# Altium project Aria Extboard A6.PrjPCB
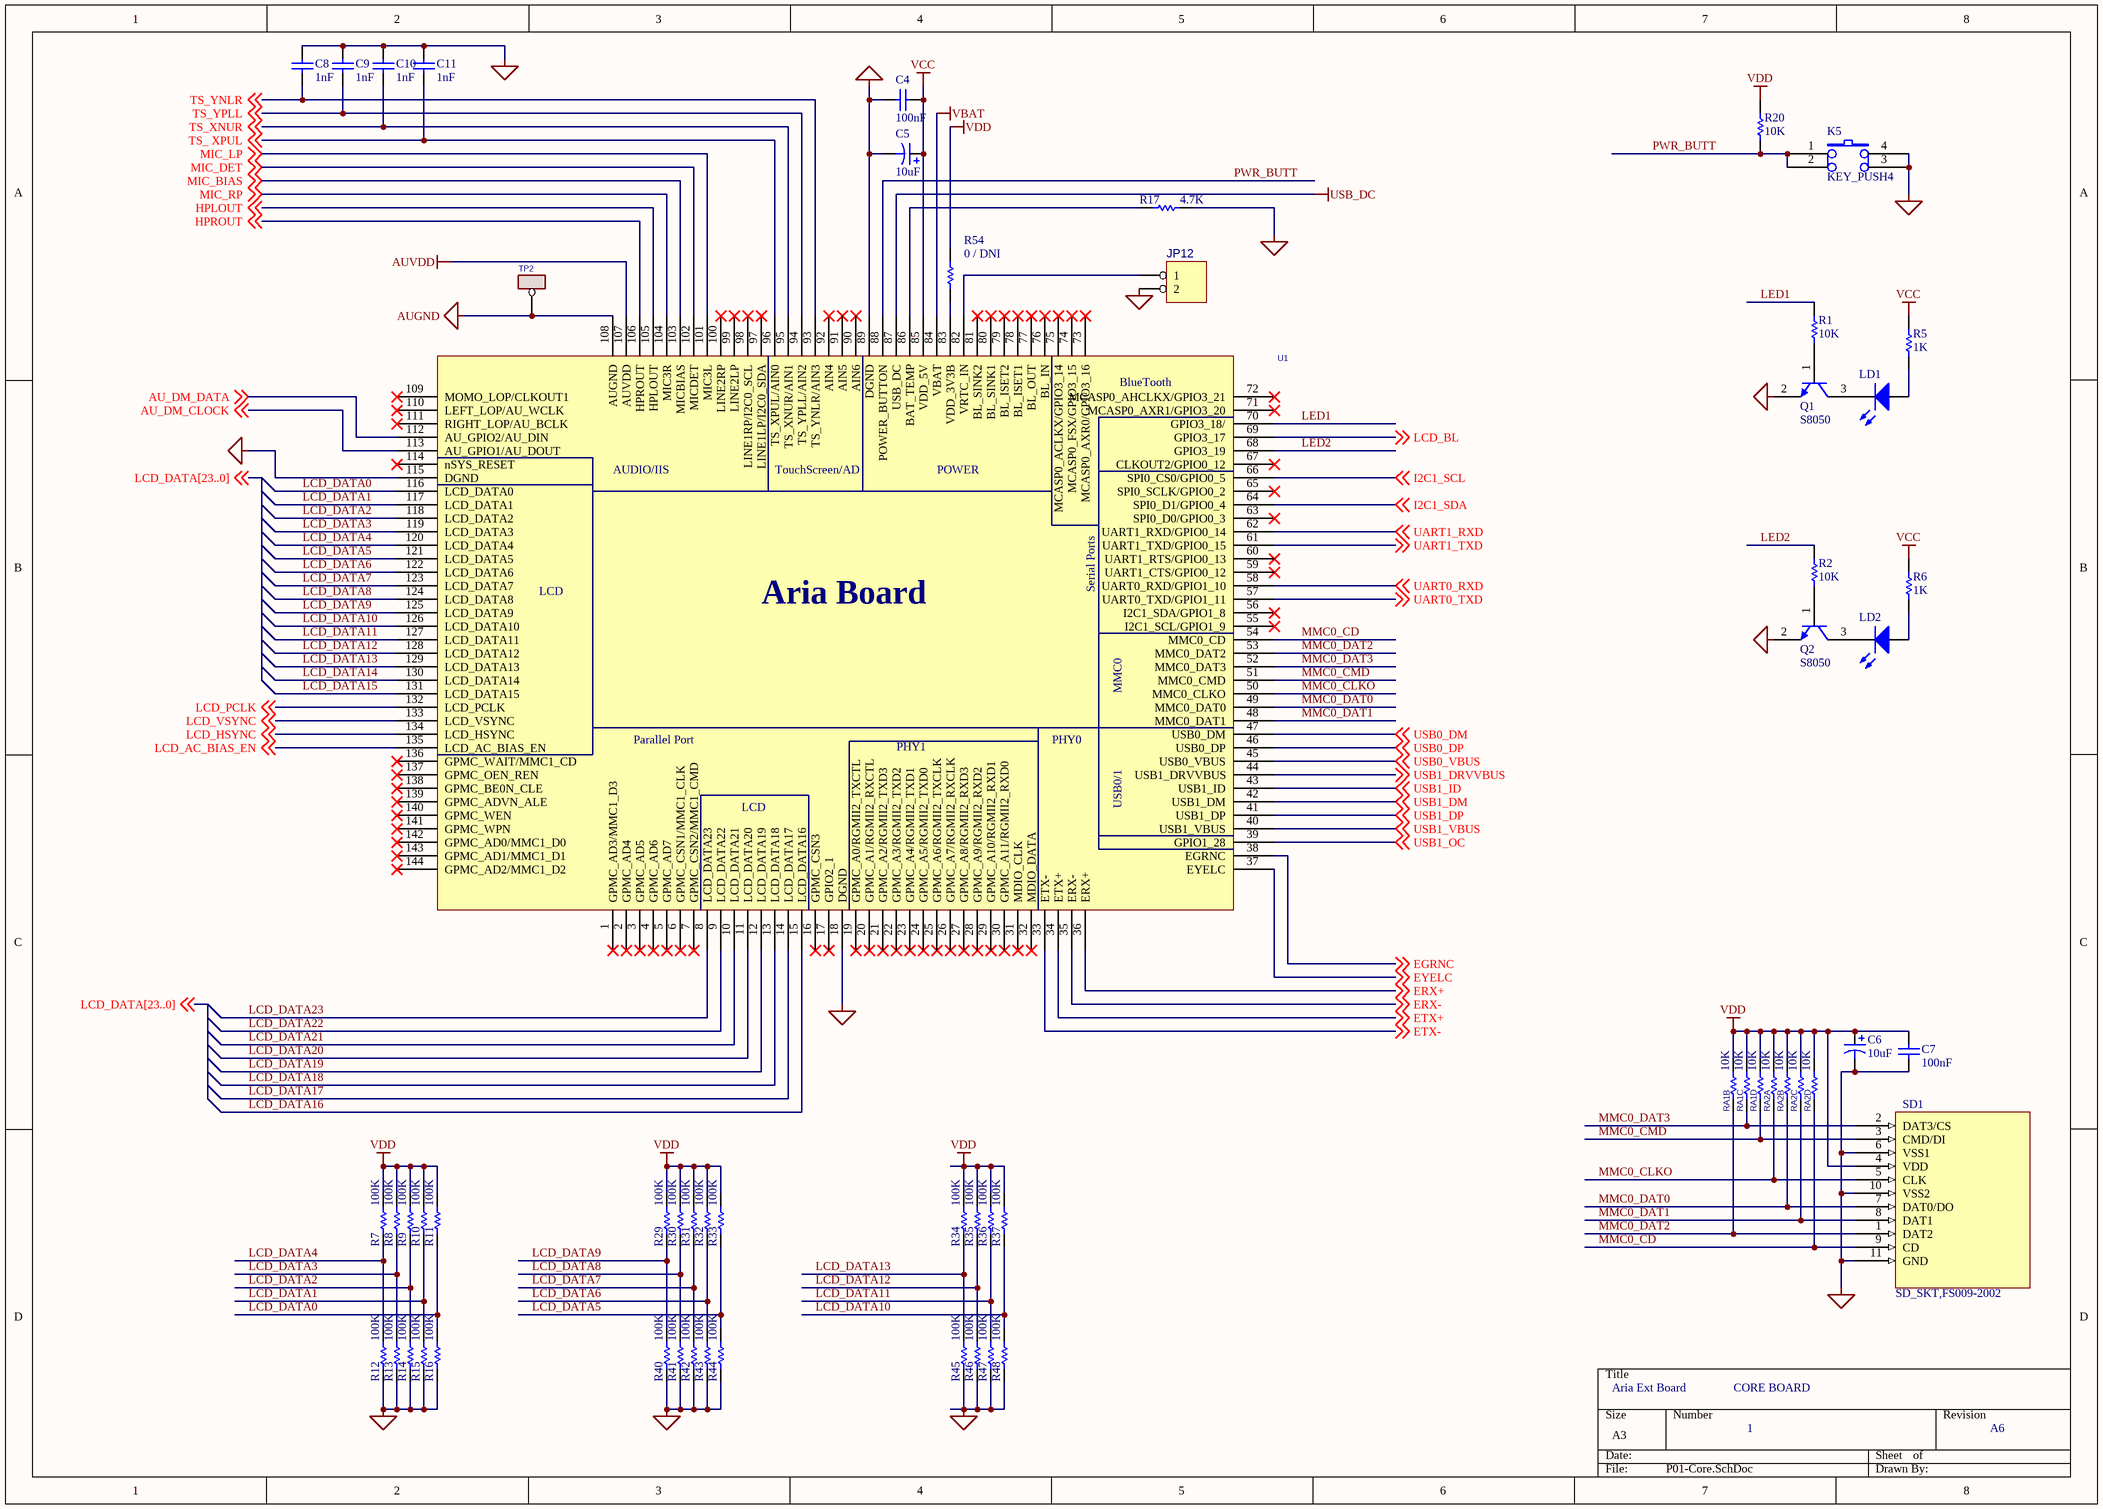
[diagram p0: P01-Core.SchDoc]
4 sheets, 128 parts. Net scope: global (net labels, ports and power ports of the same name join across sheets).
Board file: ExtBoard.PcbDoc
Sheets:
  P01-Core.SchDoc
  P02-Audio&Net.SchDoc
  P03-LCD.SchDoc
  P04-Connect.SchDoc

## Sheet P01-Core.SchDoc
size A3

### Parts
C4  100nF  [U1608-0603]
C5  10uF  [CC3216-1206]
C6  10uF  [CC3216-1206]
C7  100nF  [U1608-0603]
C8  1nF  [U1608-0603]
C9  1nF  [U1608-0603]
C10  1nF  [U1608-0603]
C11  1nF  [U1608-0603]
JP12  HEADER 2  [SIP\2P]  (value not drawn)
K5  KEY_PUSH4  [KEY6.5X6.5B]
LD1  LED  [LED1206]  (value not drawn)
LD2  LED  [LED1206]  (value not drawn)
Q1  S8050  [SOT23]
Q2  S8050  [SOT23]
R1  10K  [U1608-0603]
R2  10K  [U1608-0603]
R5  1K  [U1608-0603]
R6  1K  [U1608-0603]
R7  100K  [U1608-0603]
R8  100K  [U1608-0603]
R9  100K  [U1608-0603]
R10  100K  [U1608-0603]
R11  100K  [U1608-0603]
R12  100K  [U1608-0603]
R13  100K  [U1608-0603]
R14  100K  [U1608-0603]
R15  100K  [U1608-0603]
R16  100K  [U1608-0603]
R17  4.7K  [U1608-0603]
R20  10K  [U1608-0603]
R29  100K  [U1608-0603]
R30  100K  [U1608-0603]
R31  100K  [U1608-0603]
R32  100K  [U1608-0603]
R33  100K  [U1608-0603]
R34  100K  [U1608-0603]
R35  100K  [U1608-0603]
R36  100K  [U1608-0603]
R37  100K  [U1608-0603]
R40  100K  [U1608-0603]
R41  100K  [U1608-0603]
R42  100K  [U1608-0603]
R43  100K  [U1608-0603]
R44  100K  [U1608-0603]
R45  100K  [U1608-0603]
R46  100K  [U1608-0603]
R47  100K  [U1608-0603]
R48  100K  [U1608-0603]
R54  0 / DNI  [U1608-0603]
RA1  10K  [RP4]  (parts B,C,D of 4)
RA2  10K  [RP4]  (parts A,B,C,D of 4)
SD1  SD_SKT,FS009-2002  [DWM-1007A]
TP2  PAD  [TP10C]  (value not drawn)
U1  AM335X144-A5  [AM335X_144_50B]  (value not drawn)

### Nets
AUGND: TP2.1 U1.108(AUGND)
AUVDD: U1.107(AUVDD)
DGND: C4.1 C5.2 C6.2 C7.2 C8.2 C9.2 C10.2 C11.2 JP12.2 K5.3 K5.4 Q1.2(E) Q2.2(E) R12.2 R13.2 R14.2 R15.2 R16.2 R17.1 R40.2 R41.2 R42.2 R43.2 R44.2 R45.2 R46.2 R47.2 R48.2 SD1.6(VSS1) SD1.10(VSS2) SD1.11(GND) U1.18(DGND) U1.89(DGND) U1.115(DGND)
USB_DC: U1.45(USB0_VBUS) U1.87(USB_DC) ; off-sheet USB0_VBUS  [also labelled USB0_VBUS]
VBAT: U1.84(VBAT)
VCC: C4.2 C5.1 R5.1 R6.1 U1.85(VDD_5V)
VDD: C6.1 C7.1 R7.1 R8.1 R9.1 R10.1 R11.1 R20.1 R29.1 R30.1 R31.1 R32.1 R33.1 R34.1 R35.1 R36.1 R37.1 R54.1 RA1.5 RA1.6 RA1.7 RA2.5 RA2.6 RA2.7 RA2.8 SD1.4(VDD)
AU_DM_CLOCK: U1.113(AU_GPIO1/AU_DOUT) ; off-sheet AU_DM_CLOCK
AU_DM_DATA: U1.112(AU_GPIO2/AU_DIN) ; off-sheet AU_DM_DATA
EGRNC: U1.38(EGRNC) ; off-sheet EGRNC
ERX+: U1.36(ERX+) ; off-sheet ERX+
ERX-: U1.35(ERX-) ; off-sheet ERX-
ETX+: U1.34(ETX+) ; off-sheet ETX+
ETX-: U1.33(ETX-) ; off-sheet ETX-
EYELC: U1.37(EYELC) ; off-sheet EYELC
HPLOUT: U1.105(HPLOUT) ; off-sheet HPLOUT
HPROUT: U1.106(HPROUT) ; off-sheet HPROUT
I2C1_SCL: U1.66(SPI0_CS0/GPIO0_5) ; off-sheet I2C1_SCL
I2C1_SDA: U1.64(SPI0_D1/GPIO0_4) ; off-sheet I2C1_SDA
LCD_AC_BIAS_EN: U1.135(LCD_AC_BIAS_EN) ; off-sheet LCD_AC_BIAS_EN
LCD_BL: U1.69(GPIO3_17) ; off-sheet LCD_BL
LCD_DATA0: R11.2 R16.1 U1.116(LCD_DATA0)
LCD_DATA1: R10.2 R15.1 U1.117(LCD_DATA1)
LCD_DATA2: R9.2 R14.1 U1.118(LCD_DATA2)
LCD_DATA3: R8.2 R13.1 U1.119(LCD_DATA3)
LCD_DATA4: R7.2 R12.1 U1.120(LCD_DATA4)
LCD_DATA5: R33.2 R44.1 U1.121(LCD_DATA5)
LCD_DATA6: R32.2 R43.1 U1.122(LCD_DATA6)
LCD_DATA7: R31.2 R42.1 U1.123(LCD_DATA7)
LCD_DATA8: R30.2 R41.1 U1.124(LCD_DATA8)
LCD_DATA9: R29.2 R40.1 U1.125(LCD_DATA9)
LCD_DATA10: R37.2 R48.1 U1.126(LCD_DATA10)
LCD_DATA11: R36.2 R47.1 U1.127(LCD_DATA11)
LCD_DATA12: R35.2 R46.1 U1.128(LCD_DATA12)
LCD_DATA13: R34.2 R45.1 U1.129(LCD_DATA13)
LCD_DATA14: U1.130(LCD_DATA14)
LCD_DATA15: U1.131(LCD_DATA15)
LCD_DATA16: U1.15(LCD_DATA16)
LCD_DATA17: U1.14(LCD_DATA17)
LCD_DATA18: U1.13(LCD_DATA18)
LCD_DATA19: U1.12(LCD_DATA19)
LCD_DATA20: U1.11(LCD_DATA20)
LCD_DATA21: U1.10(LCD_DATA21)
LCD_DATA22: U1.9(LCD_DATA22)
LCD_DATA23: U1.8(LCD_DATA23)
LCD_HSYNC: U1.134(LCD_HSYNC) ; off-sheet LCD_HSYNC
LCD_PCLK: U1.132(LCD_PCLK) ; off-sheet LCD_PCLK
LCD_VSYNC: U1.133(LCD_VSYNC) ; off-sheet LCD_VSYNC
LED1: R1.1 U1.70(GPIO3_18/)
LED2: R2.1 U1.68(GPIO3_19)
MIC_BIAS: U1.103(MICBIAS) ; off-sheet MIC_BIAS
MIC_DET: U1.102(MICDET) ; off-sheet MIC_DET
MIC_LP: U1.101(MIC3L) ; off-sheet MIC_LP
MIC_RP: U1.104(MIC3R) ; off-sheet MIC_RP
MMC0_CD: RA2.4 SD1.9(CD) U1.54(MMC0_CD)
MMC0_CLKO: RA2.1 SD1.5(CLK) U1.50(MMC0_CLKO)
MMC0_CMD: RA1.4 SD1.3(CMD/DI) U1.51(MMC0_CMD)
MMC0_DAT0: RA2.2 SD1.7(DAT0/DO) U1.49(MMC0_DAT0)
MMC0_DAT1: RA2.3 SD1.8(DAT1) U1.48(MMC0_DAT1)
MMC0_DAT2: RA1.2 SD1.1(DAT2) U1.53(MMC0_DAT2)
MMC0_DAT3: RA1.3 SD1.2(DAT3/CS) U1.52(MMC0_DAT3)
PWR_BUTT: K5.1 K5.2 R20.2 U1.88(POWER_BUTTON)
TS_ XPUL: C11.1 U1.96(TS_XPUL/AIN0) ; off-sheet TS_ XPUL
TS_XNUR: C10.1 U1.95(TS_XNUR/AIN1) ; off-sheet TS_XNUR
TS_YNLR: C8.1 U1.93(TS_YNLR/AIN3) ; off-sheet TS_YNLR
TS_YPLL: C9.1 U1.94(TS_YPLL/AIN2) ; off-sheet TS_YPLL
UART0_RXD: U1.58(UART0_RXD/GPIO1_10) ; off-sheet UART0_RXD
UART0_TXD: U1.57(UART0_TXD/GPIO1_11) ; off-sheet UART0_TXD
UART1_RXD: U1.62(UART1_RXD/GPIO0_14) ; off-sheet UART1_RXD
UART1_TXD: U1.61(UART1_TXD/GPIO0_15) ; off-sheet UART1_TXD
USB0_DM: U1.47(USB0_DM) ; off-sheet USB0_DM
USB0_DP: U1.46(USB0_DP) ; off-sheet USB0_DP
USB1_DM: U1.42(USB1_DM) ; off-sheet USB1_DM
USB1_DP: U1.41(USB1_DP) ; off-sheet USB1_DP
USB1_DRVVBUS: U1.44(USB1_DRVVBUS) ; off-sheet USB1_DRVVBUS
USB1_ID: U1.43(USB1_ID) ; off-sheet USB1_ID
USB1_OC: U1.39(GPIO1_28) ; off-sheet USB1_OC
USB1_VBUS: U1.40(USB1_VBUS) ; off-sheet USB1_VBUS
NetJP12_1: JP12.1 U1.82(VRTC_IN)
NetLD1_1: LD1.1(A) R5.2
NetLD1_2: LD1.2(K) Q1.3(C)
NetLD2_1: LD2.1(A) R6.2
NetLD2_2: LD2.2(K) Q2.3(C)
NetQ1_1: Q1.1(B) R1.2
NetQ2_1: Q2.1(B) R2.2
NetR17_2: R17.2 U1.86(BAT_TEMP)
NetR54_2: R54.2 U1.83(VDD_3V3B)

Not connected (* = marked no-connect by the designer): U1 1(GPMC_AD3/MMC1_D3)* 2(GPMC_AD4)* 3(GPMC_AD5)* 4(GPMC_AD6)* 5(GPMC_AD7)* 6(GPMC_CSN1/MMC1_CLK)* 7(GPMC_CSN2/MMC1_CMD)* 16(GPMC_CSN3)* 17(GPIO2_1)* 19(GPMC_A0/RGMII2_TXCTL)* 20(GPMC_A1/RGMII2_RXCTL)* 21(GPMC_A2/RGMII2_TXD3)* 22(GPMC_A3/RGMII2_TXD2)* 23(GPMC_A4/RGMII2_TXD1)* 24(GPMC_A5/RGMII2_TXD0)* 25(GPMC_A6/RGMII2_TXCLK)* 26(GPMC_A7/RGMII2_RXCLK)* 27(GPMC_A8/RGMII2_RXD3)* 28(GPMC_A9/RGMII2_RXD2)* 29(GPMC_A10/RGMII2_RXD1)* 30(GPMC_A11/RGMII2_RXD0)* 31(MDIO_CLK)* 32(MDIO_DATA)* 55(I2C1_SCL/GPIO1_9)* 56(I2C1_SDA/GPIO1_8)* 59(UART1_CTS/GPIO0_12)* 60(UART1_RTS/GPIO0_13)* 63(SPI0_D0/GPIO0_3)* 65(SPI0_SCLK/GPIO0_2)* 67(CLKOUT2/GPIO0_12)* 71(MCASP0_AXR1/GPIO3_20)* 72(MCASP0_AHCLKX/GPIO3_21)* 73(MCASP0_AXR0/GPIO3_16)* 74(MCASP0_FSX/GPIO3_15)* 75(MCASP0_ACLKX/GPIO3_14)* 76(BL_IN)* 77(BL_OUT)* 78(BL_ISET1)* 79(BL_ISET2)* 80(BL_SINK1)* 81(BL_SINK2)* 90(AIN6)* 91(AIN5)* 92(AIN4)* 97(LINE1LP/I2C0_SDA)* 98(LINE1RP/I2C0_SCL)* 99(LINE2LP)* 100(LINE2RP)* 109(MOMO_LOP/CLKOUT1)* 110(LEFT_LOP/AU_WCLK)* 111(RIGHT_LOP/AU_BCLK)* 114(nSYS_RESET)* 136(GPMC_WAIT/MMC1_CD)* 137(GPMC_OEN_REN)* 138(GPMC_BE0N_CLE)* 139(GPMC_ADVN_ALE)* 140(GPMC_WEN)* 141(GPMC_WPN)* 142(GPMC_AD0/MMC1_D0)* 143(GPMC_AD1/MMC1_D1)* 144(GPMC_AD2/MMC1_D2)*

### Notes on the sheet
- Aria Ext Board
- CORE BOARD
- 1
- A6

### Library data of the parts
C4 C7-C11 = CAP_SIMO: Capacitor
C5 C6 = Cap Pol2: Polarized Capacitor (Axial)
JP12 = HEADER 2: Header 2 2 Pin
K5 = KEY_PUSH4: Text Field1: 30
LD1 LD2 = LED: Typical RED, GREEN, YELLOW, AMBER GaAs LED
Q1 Q2 = S8050LT1(NPN): NPN Bipolar Transistor
R1 R2 R5-R17 R20 R29-R37 R40-R48 R54 = RES1: Resistor
RA1 RA2 = RP4R
SD1 = SD_SKT_1: Text Field1: 100; Text Field2: 130
TP2 = TEST POINT_0
U1 = AM335X144-A5: Right: 60; Bottom: 750

## Sheet P02-Audio&Net.SchDoc
size A4
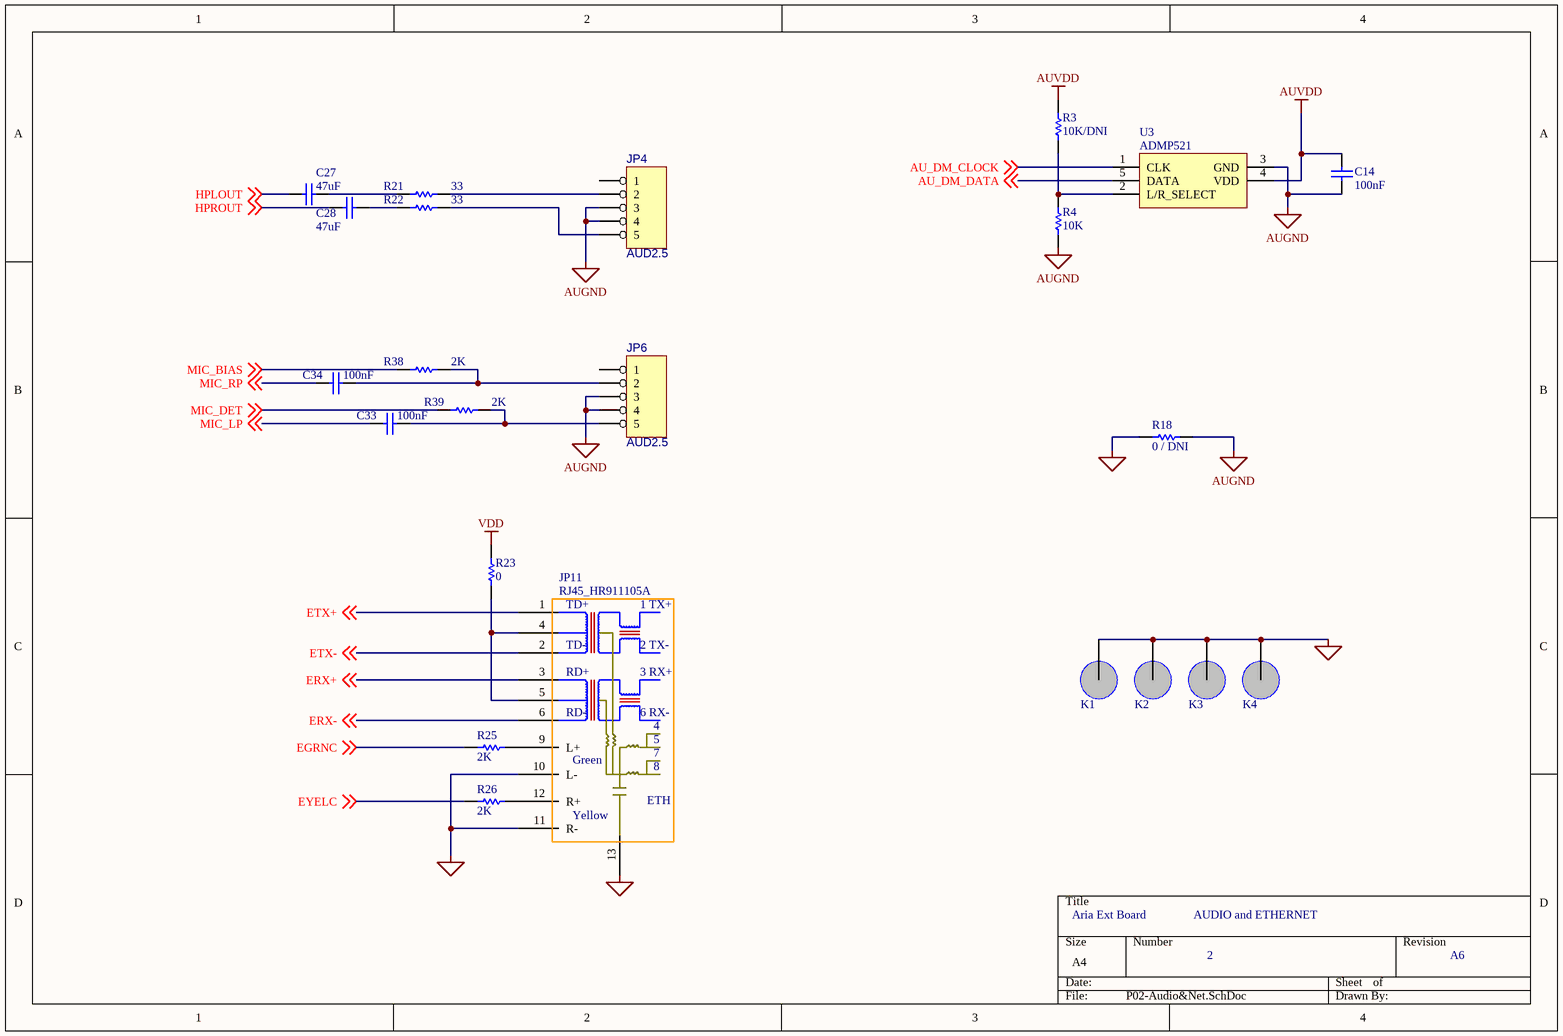
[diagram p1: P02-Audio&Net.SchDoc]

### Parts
C14  100nF  [U1608-0603]
C27  47uF  [U2012-0805]
C28  47uF  [U2012-0805]
C33  100nF  [U1608-0603]
C34  100nF  [U1608-0603]
JP4  AUD2.5  [PJ327A]
JP6  AUD2.5  [PJ327A]
JP11  RJ45_HR911105A  [RJ45_HR911105A]
K1  HOLE  [SS-TOTAL-32]  (value not drawn)
K2  HOLE  [SS-TOTAL-32]  (value not drawn)
K3  HOLE  [SS-TOTAL-32]  (value not drawn)
K4  HOLE  [SS-TOTAL-32]  (value not drawn)
R3  10K/DNI  [U1608-0603]
R4  10K  [U1608-0603]
R18  0 / DNI  [U2012-0805]
R21  33  [U1608-0603]
R22  33  [U1608-0603]
R23  0  [U1608-0603]
R25  2K  [U1608-0603]
R26  2K  [U1608-0603]
R38  2K  [U1608-0603]
R39  2K  [U1608-0603]
U3  ADMP521  [ADMP521]

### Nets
AUGND: C14.1 JP4.3 JP4.4 JP6.3 JP6.4 R4.1 R18.1 U3.3(GND)
AUVDD: C14.2 R3.2 U3.4(VDD)
DGND: JP11.10(L-) JP11.11(R-) JP11.13 K1.1(K) K2.1(K) K3.1(K) K4.1(K) R18.2
VDD: R23.1
AU_DM_CLOCK: U3.1(CLK) ; off-sheet AU_DM_CLOCK
AU_DM_DATA: U3.5(DATA) ; off-sheet AU_DM_DATA
EGRNC: R25.2 ; off-sheet EGRNC
ERX+: JP11.3 ; off-sheet ERX+
ERX-: JP11.6 ; off-sheet ERX-
ETX+: JP11.1 ; off-sheet ETX+
ETX-: JP11.2 ; off-sheet ETX-
EYELC: R26.2 ; off-sheet EYELC
HPLOUT: C27.2 ; off-sheet HPLOUT
HPROUT: C28.2 ; off-sheet HPROUT
MIC_BIAS: R38.1 ; off-sheet MIC_BIAS
MIC_DET: R39.1 ; off-sheet MIC_DET
MIC_LP: C33.2 ; off-sheet MIC_LP
MIC_RP: C34.2 ; off-sheet MIC_RP
NetC27_1: C27.1 R21.2
NetC28_1: C28.1 R22.2
NetC33_1: C33.1 JP6.5 R39.2
NetC34_1: C34.1 JP6.2 R38.2
NetJP4_2: JP4.2 R21.1
NetJP4_5: JP4.5 R22.1
NetJP11_4: JP11.4 JP11.5 R23.2
NetJP11_9: JP11.9(L+) R25.1
NetJP11_12: JP11.12(R+) R26.1
NetR3_1: R3.1 R4.2 U3.2(L/R_SELECT)

Not connected (* = marked no-connect by the designer): JP4 1; JP6 1

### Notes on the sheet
- Aria Ext Board
- AUDIO and ETHERNET
- 2
- A6

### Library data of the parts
C14 C27 C28 C33 C34 = CAP_SIMO: Capacitor
JP4 JP6 = AUD2.5: Header 5
R3 R4 R18 R21-R23 R25 R26 R38 R39 = RES1: Resistor

## Sheet P03-LCD.SchDoc
size A4
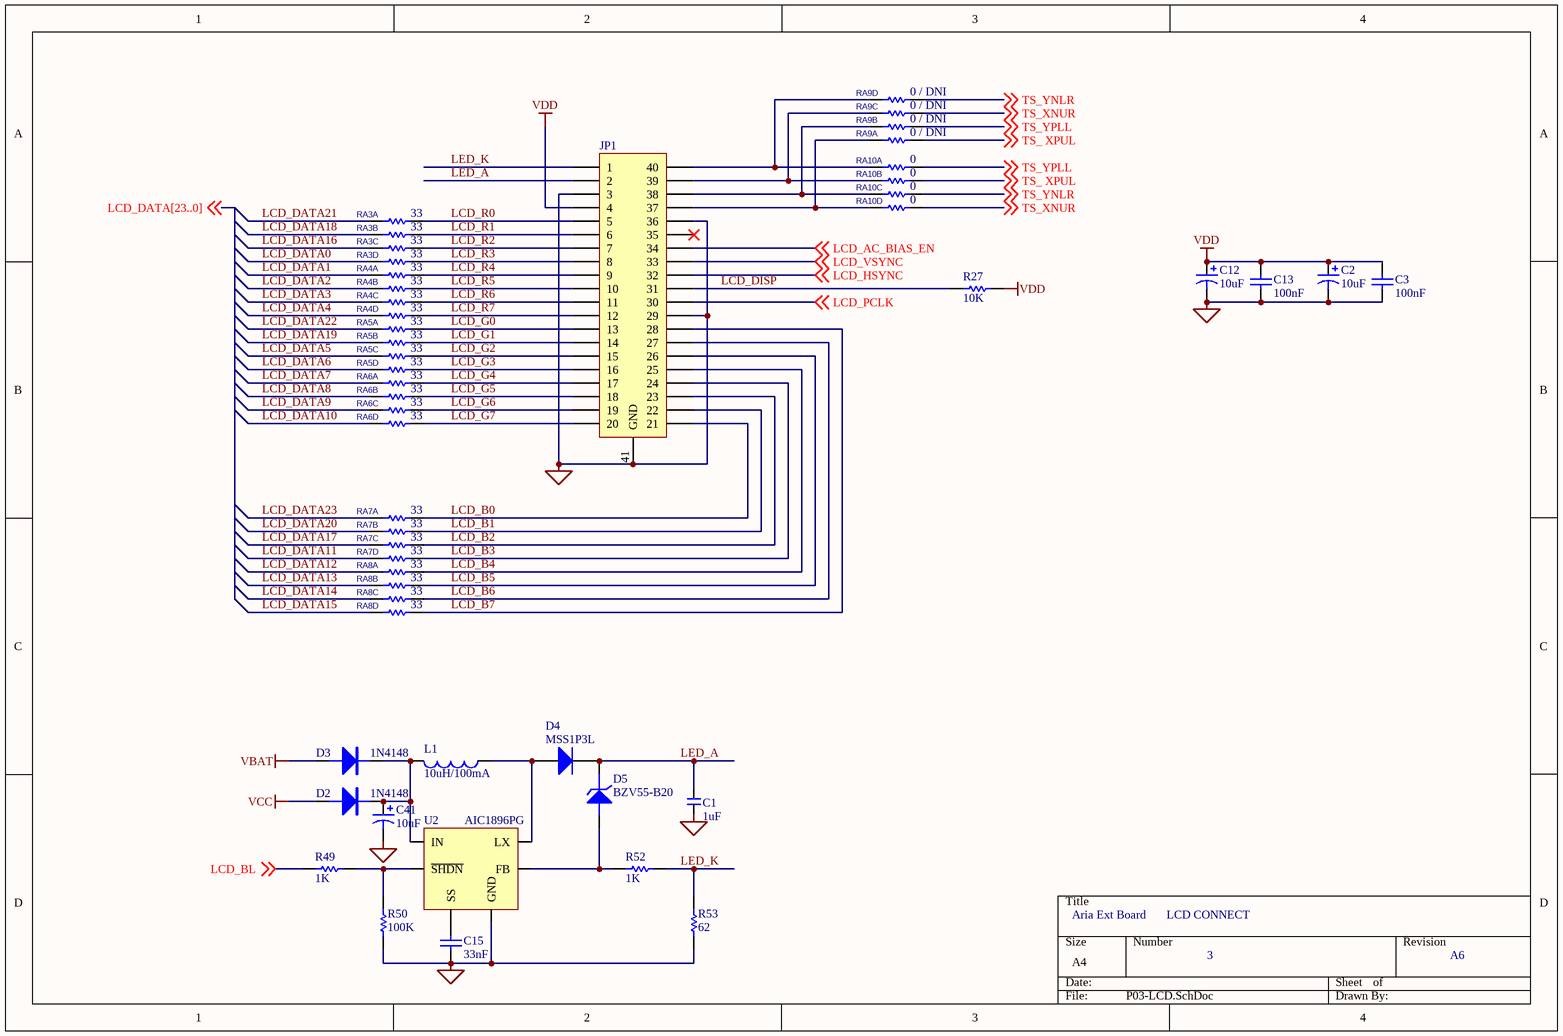
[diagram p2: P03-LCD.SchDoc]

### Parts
C1  1uF  [U2012-0805]
C2  10uF  [CC3216-1206]
C3  100nF  [U1608-0603]
C12  10uF  [CC3216-1206]
C13  100nF  [U1608-0603]
C15  33nF  [U1608-0603]
C41  10uF  [CC3216-1206]
D2  1N4148  [LED1206]
D3  1N4148  [LED1206]
D4  MSS1P3L  [DI1206]
D5  BZV55-B20  [DI1206]
JP1  HEADER 40  [FFC0.5-40TOP]  (value not drawn)
L1  10uH/100mA  [L5*5]
R27  10K  [U1608-0603]
R49  1K  [U1608-0603]
R50  100K  [U1608-0603]
R52  1K  [U1608-0603]
R53  62  [U1608-0603]
RA3  33  [RP4]  (parts A,B,C,D of 4)
RA4  33  [RP4]  (parts A,B,C,D of 4)
RA5  33  [RP4]  (parts A,B,C,D of 4)
RA6  33  [RP4]  (parts A,B,C,D of 4)
RA7  33  [RP4]  (parts A,B,C,D of 4)
RA8  33  [RP4]  (parts A,B,C,D of 4)
RA9  0 / DNI  [RP4]  (parts A,B,C,D of 4)
RA10  0  [RP4]  (parts A,B,C,D of 4)
U2  AIC1896PG  [SOT_26]

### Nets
DGND: C1.2 C2.2 C3.1 C12.2 C13.1 C15.1 C41.2 JP1.3 JP1.29 JP1.36 JP1.41(GND) R50.1 R53.1 U2.2(GND)
VBAT: D3.1(A)
VCC: D2.1(A)
VDD: C2.1 C3.2 C12.1 C13.2 JP1.4 R27.2
LCD_AC_BIAS_EN: JP1.34 ; off-sheet LCD_AC_BIAS_EN
LCD_B0: JP1.21 RA7.1
LCD_B1: JP1.22 RA7.2
LCD_B2: JP1.23 RA7.3
LCD_B3: JP1.24 RA7.4
LCD_B4: JP1.25 RA8.1
LCD_B5: JP1.26 RA8.2
LCD_B6: JP1.27 RA8.3
LCD_B7: JP1.28 RA8.4
LCD_BL: R49.1 ; off-sheet LCD_BL
LCD_DATA0: RA3.5
LCD_DATA1: RA4.8
LCD_DATA2: RA4.7
LCD_DATA3: RA4.6
LCD_DATA4: RA4.5
LCD_DATA5: RA5.6
LCD_DATA6: RA5.5
LCD_DATA7: RA6.8
LCD_DATA8: RA6.7
LCD_DATA9: RA6.6
LCD_DATA10: RA6.5
LCD_DATA11: RA7.5
LCD_DATA12: RA8.8
LCD_DATA13: RA8.7
LCD_DATA14: RA8.6
LCD_DATA15: RA8.5
LCD_DATA16: RA3.6
LCD_DATA17: RA7.6
LCD_DATA18: RA3.7
LCD_DATA19: RA5.7
LCD_DATA20: RA7.7
LCD_DATA21: RA3.8
LCD_DATA22: RA5.8
LCD_DATA23: RA7.8
LCD_DISP: JP1.31 R27.1
LCD_G0: JP1.13 RA5.1
LCD_G1: JP1.14 RA5.2
LCD_G2: JP1.15 RA5.3
LCD_G3: JP1.16 RA5.4
LCD_G4: JP1.17 RA6.1
LCD_G5: JP1.18 RA6.2
LCD_G6: JP1.19 RA6.3
LCD_G7: JP1.20 RA6.4
LCD_HSYNC: JP1.32 ; off-sheet LCD_HSYNC
LCD_PCLK: JP1.30 ; off-sheet LCD_PCLK
LCD_R0: JP1.5 RA3.1
LCD_R1: JP1.6 RA3.2
LCD_R2: JP1.7 RA3.3
LCD_R3: JP1.8 RA3.4
LCD_R4: JP1.9 RA4.1
LCD_R5: JP1.10 RA4.2
LCD_R6: JP1.11 RA4.3
LCD_R7: JP1.12 RA4.4
LCD_VSYNC: JP1.33 ; off-sheet LCD_VSYNC
LED_A: C1.1 D4.2(K) D5.2(K) JP1.2
LED_K: JP1.1 R52.2 R53.2
TS_ XPUL: RA9.1 RA10.7 ; off-sheet TS_ XPUL
TS_XNUR: RA9.3 RA10.4 ; off-sheet TS_XNUR
TS_YNLR: RA9.4 RA10.3 ; off-sheet TS_YNLR
TS_YPLL: RA9.2 RA10.8 ; off-sheet TS_YPLL
NetC15_2: C15.2 U2.5(SS)
NetC41_1: C41.1 D2.2(K) D3.2(K) L1.2 U2.6(IN)
NetD4_1: D4.1(A) L1.1 U2.1(LX)
NetD5_1: D5.1(A) R52.1 U2.3(FB)
NetJP1_37: JP1.37 RA9.8 RA10.5
NetJP1_38: JP1.38 RA9.7 RA10.6
NetJP1_39: JP1.39 RA9.6 RA10.2
NetJP1_40: JP1.40 RA9.5 RA10.1
NetR49_2: R49.2 R50.2 U2.4(~{SHDN})

Not connected (* = marked no-connect by the designer): JP1 35*

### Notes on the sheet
- Aria Ext Board
- LCD CONNECT
- 3
- A6

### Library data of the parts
C1 = CAP_01
C2 C12 C41 = Cap Pol2: Polarized Capacitor (Axial)
C3 C13 C15 = CAP_SIMO: Capacitor
D2 D3 = 1N4148: Diode
D4 = DIODE: Default Diode
D5 = DIO-SOD80ZENER: Text Field1: D/XXX/SOD80/PHILIPS; Text Field2: XXXv
JP1 = HEADER 40: Header, 40-Pin
L1 = INDUCTOR
R27 R49 R50 R52 R53 = RES1: Resistor
RA3-RA10 = RP4R
U2 = AIC1896

## Sheet P04-Connect.SchDoc
size A4
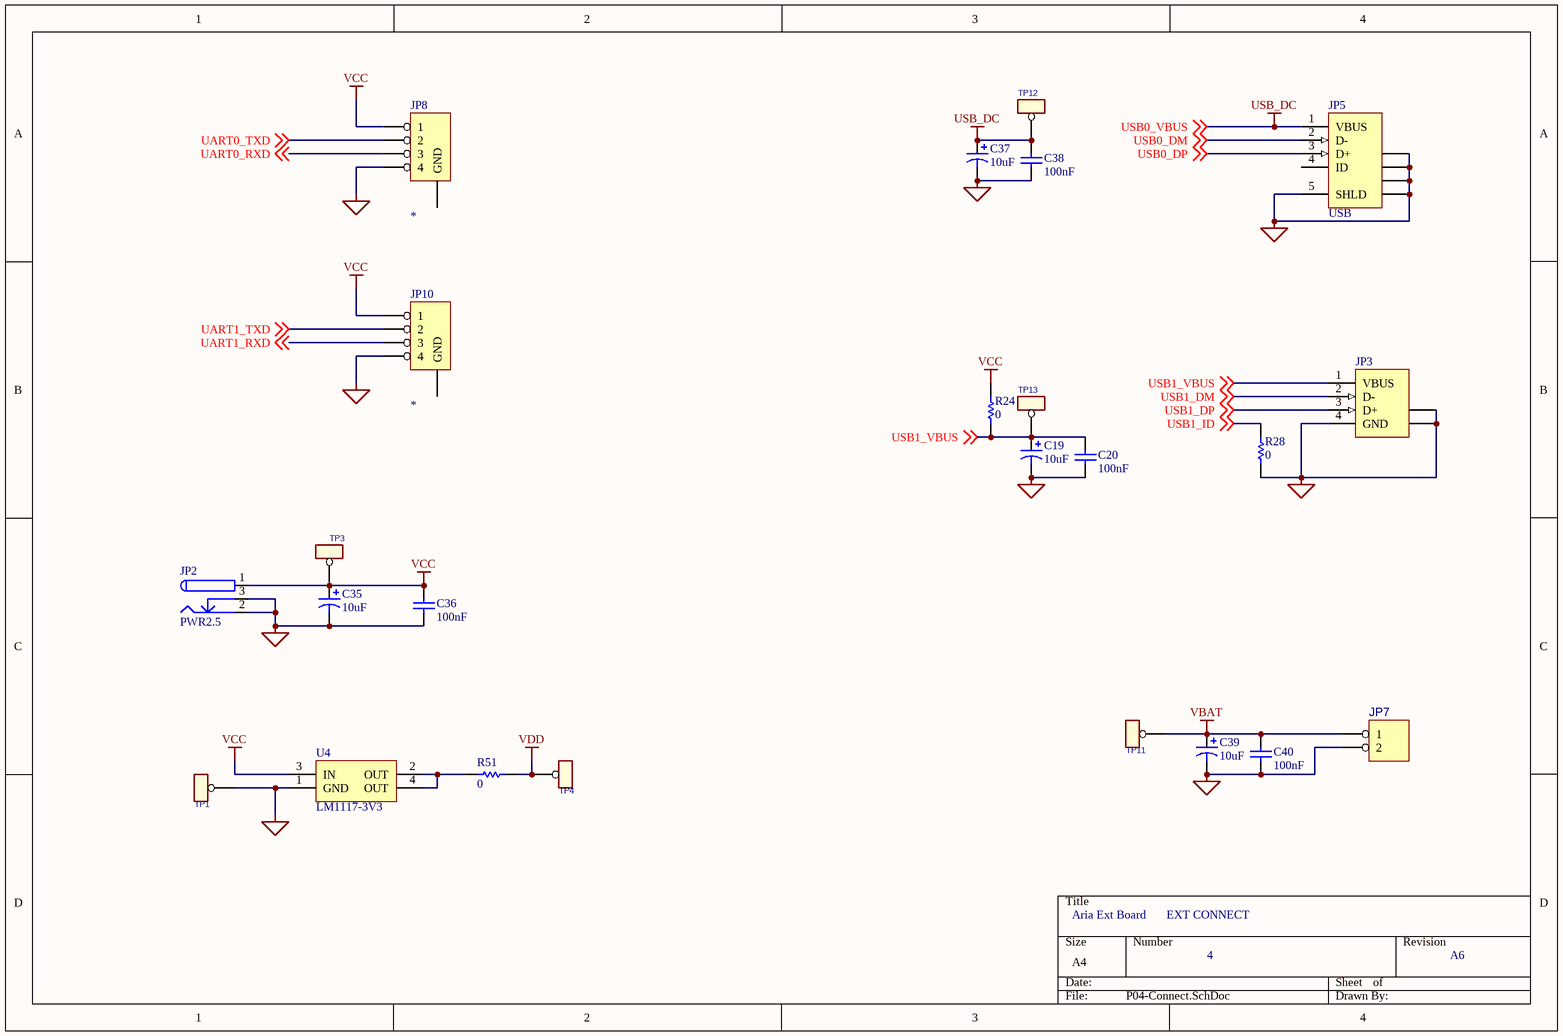
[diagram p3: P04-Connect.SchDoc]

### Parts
C19  10uF  [CC3216-1206]
C20  100nF  [U1608-0603]
C35  10uF  [CC3216-1206]
C36  100nF  [U1608-0603]
C37  10uF  [CC3216-1206]
C38  100nF  [U1608-0603]
C39  10uF  [CC3216-1206]
C40  100nF  [U1608-0603]
JP2  PWR2.5  [POWER]
JP3  USB  [USB-A_1]  (value not drawn)
JP5  USB  [USB_SM]
JP7  HEADER 2  [CON-25/02/tC]  (value not drawn)
JP8  HEADER 4  [CON-25/04/TC]  (value not drawn)
JP10  HEADER 4  [CON-25/04/TC]  (value not drawn)
R24  0  [U1608-0603]
R28  0  [U1608-0603]
R51  0  [U1608-0603]
TP1  PAD  [TP10C]  (value not drawn)
TP3  PAD  [TP10C]  (value not drawn)
TP4  PAD  [TP10C]  (value not drawn)
TP11  PAD  [TP10C]  (value not drawn)
TP12  PAD  [TP10C]  (value not drawn)
TP13  PAD  [TP10C]  (value not drawn)
U4  LM1117-3V3  [SOT223]

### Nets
DGND: C19.2 C20.1 C35.2 C36.1 C37.2 C38.1 C39.2 C40.1 JP2.2 JP2.3 JP3.4(GND) JP3.5(SHLD) JP3.6(SHLD) JP5.5(SHLD) JP5.6(SHLD) JP5.7(SHLD) JP5.8(SHLD) JP5.9(SHLD) JP7.2 JP8.4 JP10.4 R28.2 TP1.1 U4.1(GND)
USB_DC: C37.1 C38.2 JP5.1(VBUS) TP12.1 ; off-sheet USB0_VBUS  [also labelled USB0_VBUS]
VBAT: C39.1 C40.2 JP7.1 TP11.1
VCC: C35.1 C36.2 JP2.1 JP8.1 JP10.1 R24.1 TP3.1 U4.3(IN)
VDD: R51.2 TP4.1
UART0_RXD: JP8.3 ; off-sheet UART0_RXD
UART0_TXD: JP8.2 ; off-sheet UART0_TXD
UART1_RXD: JP10.3 ; off-sheet UART1_RXD
UART1_TXD: JP10.2 ; off-sheet UART1_TXD
USB0_DM: JP5.2(D-) ; off-sheet USB0_DM
USB0_DP: JP5.3(D+) ; off-sheet USB0_DP
USB1_DM: JP3.2(D-) ; off-sheet USB1_DM
USB1_DP: JP3.3(D+) ; off-sheet USB1_DP
USB1_ID: R28.1 ; off-sheet USB1_ID
USB1_VBUS: C19.1 C20.2 JP3.1(VBUS) R24.2 TP13.1 ; off-sheet USB1_VBUS
NetR51_1: R51.1 U4.2(OUT) U4.4(OUT)

Not connected (* = marked no-connect by the designer): JP5 4(ID); JP8 5(GND); JP10 5(GND)

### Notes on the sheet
- Aria Ext Board
- EXT CONNECT
- 4
- A6

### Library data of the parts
C19 C35 C37 C39 = Cap Pol2: Polarized Capacitor (Axial)
C20 C36 C38 C40 = CAP_SIMO: Capacitor
JP2 = PWR2.5: Low Voltage Power Supply Connector
JP3 = USB_HOST: USB 1.1, Right Angle, Thru-Hole, A Type, Receptacle, 4 Position, Black; ContactMaterial: Copper Alloy; ContactPlating: Gold Flash over Palladium Nickel or Gold (30) over Nickel; TerminationLength: 2.29mm [0.090in.]; PCB_Layout: Complies with manufacturer's recommendation.; DrillSize: Corresponds to nominal value.; PanelGround: Without
JP5 = USB_SM: USB 2.0, Right Angle, SMT, B Type, Receptacle, 5 Position, Black; ContactMaterial: Copper Alloy; ContactPlating: Gold (30); PCB_Layout: Complies with manufacturer's recommendation.; DrillSize: Corresponds to nominal value.; PanelGround: Without
JP7 = HEADER 2: Header 2 2 Pin
JP8 JP10 = HEADER 4: Header, 4-Pin
R24 R28 R51 = RES1: Resistor
TP1 TP3 TP4 TP11-TP13 = TEST POINT_0
U4 = LM1117: 800mA and 1A Low Dropout Positive Regulator 2.85V, 3.3V, 5V, and Adjustable; PackageDocument: revC

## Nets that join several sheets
AUGND: P01-Core (TP2.1 U1.108), P02-Audio&Net (8 pins)
AUVDD: P01-Core (U1.107), P02-Audio&Net (C14.2 R3.2 U3.4)
DGND: P01-Core (34 pins), P02-Audio&Net (8 pins), P03-LCD (14 pins), P04-Connect (24 pins)
USB_DC: P01-Core (U1.45 U1.87), P04-Connect (C37.1 C38.2 JP5.1 TP12.1)
VBAT: P01-Core (U1.84), P03-LCD (D3.1), P04-Connect (C39.1 C40.2 JP7.1 TP11.1)
VCC: P01-Core (5 pins), P03-LCD (D2.1), P04-Connect (8 pins)
VDD: P01-Core (26 pins), P02-Audio&Net (R23.1), P03-LCD (6 pins), P04-Connect (R51.2 TP4.1)
AU_DM_CLOCK: P01-Core (U1.113), P02-Audio&Net (U3.1)
AU_DM_DATA: P01-Core (U1.112), P02-Audio&Net (U3.5)
EGRNC: P01-Core (U1.38), P02-Audio&Net (R25.2)
ERX+: P01-Core (U1.36), P02-Audio&Net (JP11.3)
ERX-: P01-Core (U1.35), P02-Audio&Net (JP11.6)
ETX+: P01-Core (U1.34), P02-Audio&Net (JP11.1)
ETX-: P01-Core (U1.33), P02-Audio&Net (JP11.2)
EYELC: P01-Core (U1.37), P02-Audio&Net (R26.2)
HPLOUT: P01-Core (U1.105), P02-Audio&Net (C27.2)
HPROUT: P01-Core (U1.106), P02-Audio&Net (C28.2)
LCD_AC_BIAS_EN: P01-Core (U1.135), P03-LCD (JP1.34)
LCD_BL: P01-Core (U1.69), P03-LCD (R49.1)
LCD_DATA0: P01-Core (R11.2 R16.1 U1.116), P03-LCD (RA3.5)
LCD_DATA1: P01-Core (R10.2 R15.1 U1.117), P03-LCD (RA4.8)
LCD_DATA2: P01-Core (R9.2 R14.1 U1.118), P03-LCD (RA4.7)
LCD_DATA3: P01-Core (R8.2 R13.1 U1.119), P03-LCD (RA4.6)
LCD_DATA4: P01-Core (R7.2 R12.1 U1.120), P03-LCD (RA4.5)
LCD_DATA5: P01-Core (R33.2 R44.1 U1.121), P03-LCD (RA5.6)
LCD_DATA6: P01-Core (R32.2 R43.1 U1.122), P03-LCD (RA5.5)
LCD_DATA7: P01-Core (R31.2 R42.1 U1.123), P03-LCD (RA6.8)
LCD_DATA8: P01-Core (R30.2 R41.1 U1.124), P03-LCD (RA6.7)
LCD_DATA9: P01-Core (R29.2 R40.1 U1.125), P03-LCD (RA6.6)
LCD_DATA10: P01-Core (R37.2 R48.1 U1.126), P03-LCD (RA6.5)
LCD_DATA11: P01-Core (R36.2 R47.1 U1.127), P03-LCD (RA7.5)
LCD_DATA12: P01-Core (R35.2 R46.1 U1.128), P03-LCD (RA8.8)
LCD_DATA13: P01-Core (R34.2 R45.1 U1.129), P03-LCD (RA8.7)
LCD_DATA14: P01-Core (U1.130), P03-LCD (RA8.6)
LCD_DATA15: P01-Core (U1.131), P03-LCD (RA8.5)
LCD_DATA16: P01-Core (U1.15), P03-LCD (RA3.6)
LCD_DATA17: P01-Core (U1.14), P03-LCD (RA7.6)
LCD_DATA18: P01-Core (U1.13), P03-LCD (RA3.7)
LCD_DATA19: P01-Core (U1.12), P03-LCD (RA5.7)
LCD_DATA20: P01-Core (U1.11), P03-LCD (RA7.7)
LCD_DATA21: P01-Core (U1.10), P03-LCD (RA3.8)
LCD_DATA22: P01-Core (U1.9), P03-LCD (RA5.8)
LCD_DATA23: P01-Core (U1.8), P03-LCD (RA7.8)
LCD_HSYNC: P01-Core (U1.134), P03-LCD (JP1.32)
LCD_PCLK: P01-Core (U1.132), P03-LCD (JP1.30)
LCD_VSYNC: P01-Core (U1.133), P03-LCD (JP1.33)
MIC_BIAS: P01-Core (U1.103), P02-Audio&Net (R38.1)
MIC_DET: P01-Core (U1.102), P02-Audio&Net (R39.1)
MIC_LP: P01-Core (U1.101), P02-Audio&Net (C33.2)
MIC_RP: P01-Core (U1.104), P02-Audio&Net (C34.2)
TS_ XPUL: P01-Core (C11.1 U1.96), P03-LCD (RA9.1 RA10.7)
TS_XNUR: P01-Core (C10.1 U1.95), P03-LCD (RA9.3 RA10.4)
TS_YNLR: P01-Core (C8.1 U1.93), P03-LCD (RA9.4 RA10.3)
TS_YPLL: P01-Core (C9.1 U1.94), P03-LCD (RA9.2 RA10.8)
UART0_RXD: P01-Core (U1.58), P04-Connect (JP8.3)
UART0_TXD: P01-Core (U1.57), P04-Connect (JP8.2)
UART1_RXD: P01-Core (U1.62), P04-Connect (JP10.3)
UART1_TXD: P01-Core (U1.61), P04-Connect (JP10.2)
USB0_DM: P01-Core (U1.47), P04-Connect (JP5.2)
USB0_DP: P01-Core (U1.46), P04-Connect (JP5.3)
USB1_DM: P01-Core (U1.42), P04-Connect (JP3.2)
USB1_DP: P01-Core (U1.41), P04-Connect (JP3.3)
USB1_ID: P01-Core (U1.43), P04-Connect (R28.1)
USB1_VBUS: P01-Core (U1.40), P04-Connect (5 pins)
